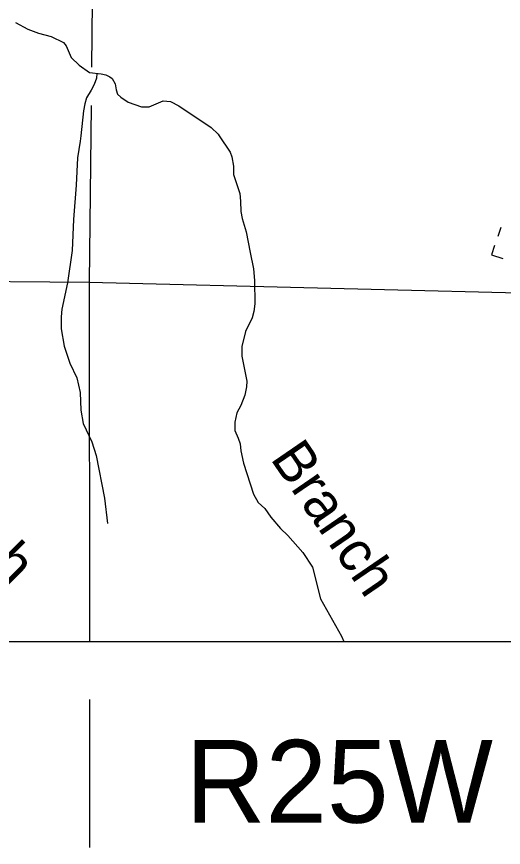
# Model space of a CAD drawing. Extents: x 0 to 3171, y 0 to 2059.
# Drawn here: x 1872.3 to 1957, y 218.6 to 363.2 of the extents above; entities that cross this region are included whole.
import ezdxf

# ---------------------------------------------------------------- set-up
doc = ezdxf.new("R2010")
doc.units = 0
for name, color, linetype in [('Default', 7, 'Continuous'), ('Level 30', 7, 'Continuous'), ('Level 35', 7, 'Continuous'), ('Level 4', 7, 'Continuous'), ('Level 5', 7, 'Continuous'), ('Level 57', 7, 'Continuous')]:
    doc.layers.add(name, color=color, linetype=linetype)

msp = doc.modelspace()

# ---------------------------------------------------------------- linework, layer by layer
at = {"layer": 'Default'}
for p, q in [((1029.42, 254.41), (2119.81, 254.41)), ((1884.96, 244.3), (1884.96, 218.57))]:
    msp.add_line(p, q, dxfattribs=at)
msp.add_lwpolyline([(2119.81, 1254.61), (1029.42, 1254.61), (1029.42, 254.41), (2119.81, 254.41)], close=True, dxfattribs=at)
msp.add_lwpolyline([(2119.81, 1254.61), (1029.42, 1254.61), (1029.42, 254.41), (2119.81, 254.41)], close=True, dxfattribs=at)
msp.add_lwpolyline([(2119.81, 1254.61), (1029.42, 1254.61), (1029.42, 254.41), (2119.81, 254.41)], close=True, dxfattribs=at)
at = {"layer": 'Level 35'}
for points in [[(1872.08, 362.16), (1874.24, 361.04), (1876.07, 360.34), (1878.3, 359.75), (1880.43, 358.72), (1880.91, 358.14), (1881.75, 356.06), (1883.15, 354.75), (1884.99, 353.47), (1886.97, 353.24), (1887.8, 353.06), (1888.52, 352.72), (1888.88, 352.43), (1889.41, 351.5), (1889.58, 350.47), (1889.86, 349.71), (1890.39, 349.19), (1891.7, 348.31), (1894.01, 347.49), (1895.34, 347.51), (1897.81, 348.54), (1899.06, 348.4), (1900.53, 347.68), (1906.12, 343.91), (1907.37, 342.74), (1907.55, 342.46)], [(1886.26, 353.3), (1886.2, 352.51), (1885.79, 351.4), (1885.26, 350.39), (1884.43, 349.06), (1884.12, 348), (1883.92, 346.83), (1883.46, 342.46)], [(1883.46, 342.46), (1883.36, 341.52), (1882.85, 338.63), (1882.63, 333.88), (1882.17, 327.9), (1881.94, 322.48), (1881.12, 316.86), (1880.12, 312.25), (1880.03, 310.96), (1880.05, 308.83), (1880.56, 305.85), (1881.56, 302.87), (1882.73, 300.29), (1883.31, 297.79), (1883.45, 294.71), (1883.88, 292.38), (1885.34, 289.18), (1886.1, 286.77), (1887.57, 279.35), (1888.08, 274.94)], [(1907.55, 342.46), (1909.43, 339.61), (1909.73, 338.78), (1910.01, 337.17), (1910.05, 335.73), (1911.13, 332.4), (1911.27, 331.06), (1911.29, 329.27), (1911.55, 328.06), (1912.23, 325.72), (1912.96, 322.14), (1913.52, 319.28), (1913.69, 317.27), (1913.75, 313.19), (1913.56, 311.85), (1913.3, 310.79), (1912.12, 308.37), (1911.51, 305.78), (1911.47, 304.09), (1912.35, 299.74), (1912.29, 298.73), (1911.99, 297.32), (1911.28, 295.52), (1910.64, 294.23), (1910.24, 292.59), (1910.27, 291.12), (1910.87, 289.8), (1911.19, 288.84), (1911.31, 287.61), (1911.76, 285.45), (1913.51, 280.08), (1914.35, 278.61), (1915.47, 277.55), (1916.53, 276.04)], [(1916.53, 276.04), (1918.19, 274.1), (1919.51, 272.86), (1922.08, 269.92), (1923.8, 267.37), (1925.19, 261.85), (1928.84, 255.33), (1929.24, 254.41)]]:
    msp.add_lwpolyline(points, dxfattribs=at)
at = {"layer": 'Level 4'}
for points in [[(1886.39, 475.86), (1885.85, 405.77), (1885.31, 354.42)], [(1885.24, 347.75), (1884.91, 316.95), (1884.96, 254.41)]]:
    msp.add_lwpolyline(points, dxfattribs=at)
at = {"layer": 'Level 5'}
for points in [[(1829.93, 317.42), (1884.91, 316.95)], [(1884.91, 316.95), (1969.04, 314.88)]]:
    msp.add_lwpolyline(points, dxfattribs=at)
at = {"layer": 'Level 57'}
msp.add_line((1956.59, 326.49), (1956.04, 324.91), dxfattribs=at)
msp.add_lwpolyline([(1955.49, 323.33), (1954.93, 321.76), (1956.9, 321.07)], dxfattribs=at)

# ---------------------------------------------------------------- texts
at = {"layer": 'Level 30'}
msp.add_text('R25W', height=14.4, dxfattribs=at).set_placement((1901.7, 222.87))
at = {"layer": 'Level 35'}
for rotation, p in [(314.9407, (1850.12, 284.85)), (304.4322, (1916.32, 286.28))]:
    msp.add_text('Branch', height=7.04, rotation=rotation, dxfattribs=at).set_placement(p)

doc.saveas('drawing.dxf')
